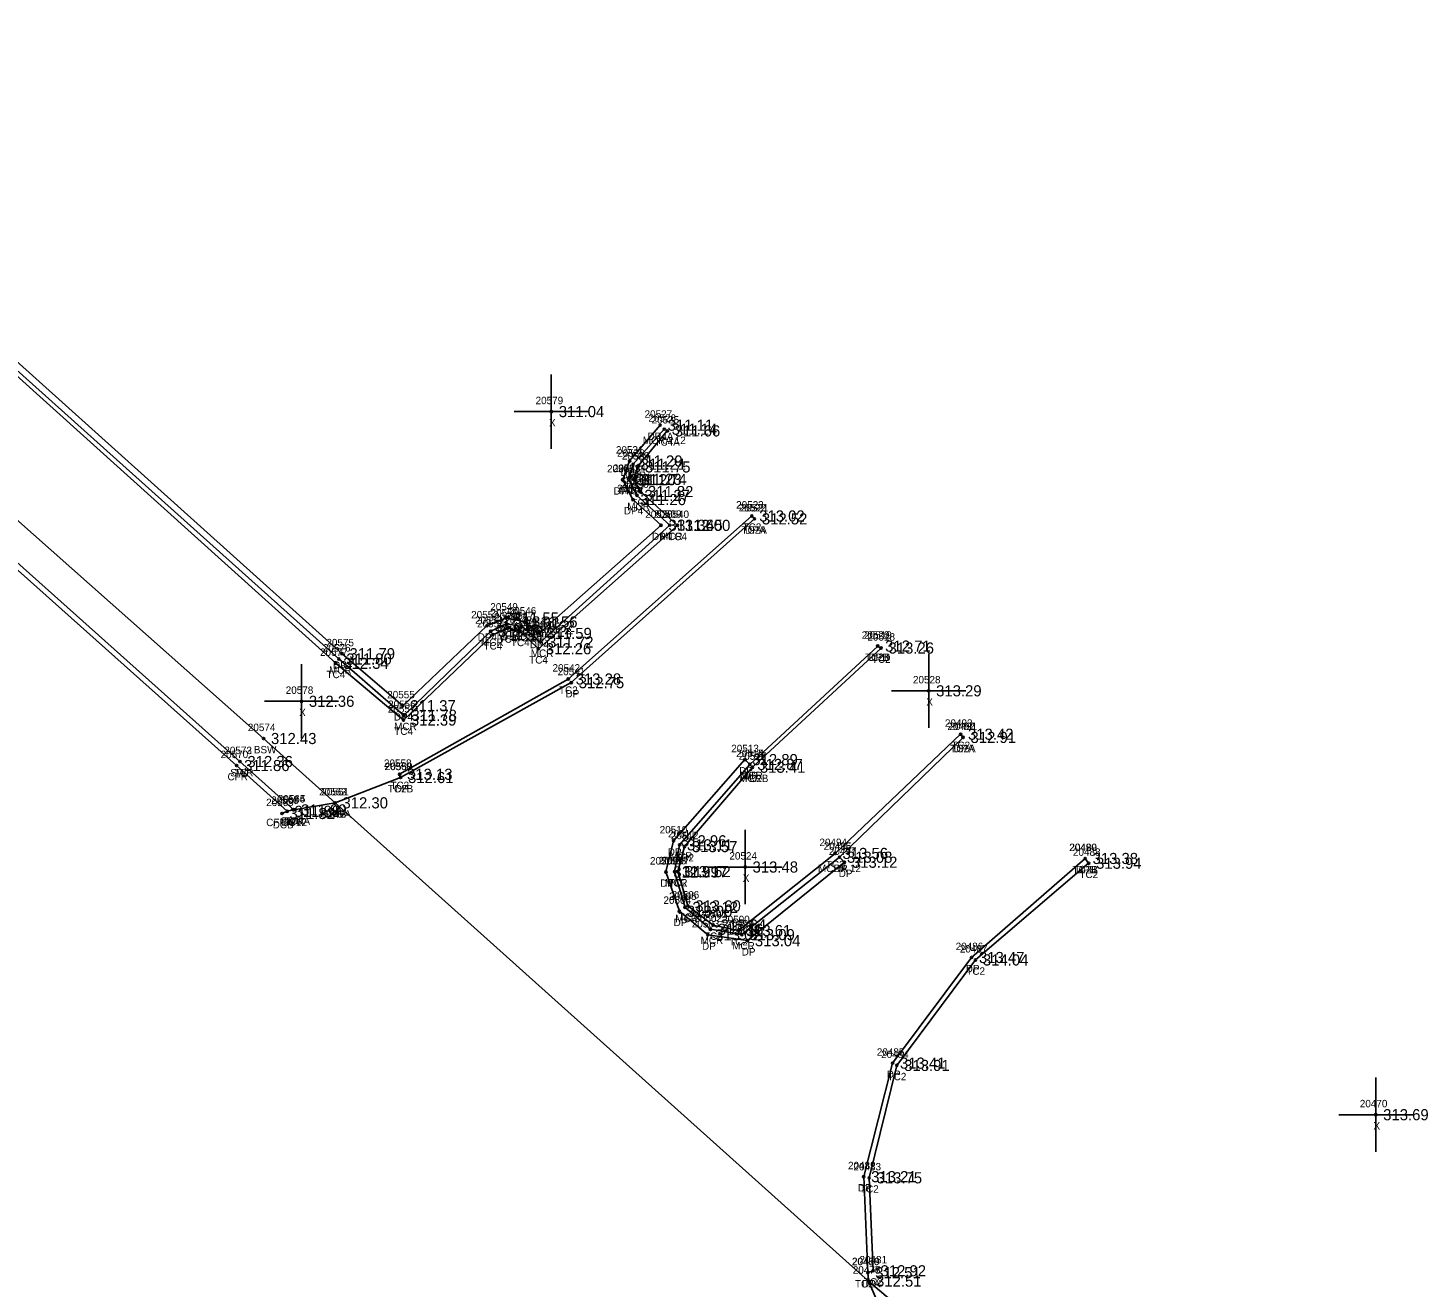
# Model space of a CAD drawing. Extents: x 1970242 to 1971082, y 803104 to 803947.
# Drawn here: x 1970893.2 to 1971082, y 803233.1 to 803402.9 of the extents above; entities that cross this region are included whole.
import ezdxf

# ---------------------------------------------------------------- set-up
doc = ezdxf.new("R2010")
doc.units = 0
for name, color, linetype in [('RD_DTM_BkLn2', 7, 'Continuous'), ('RD_EX_Conc', 7, 'Continuous'), ('RD_EX_Conc_txCode', 7, 'Continuous'), ('RD_EX_Driveway', 7, 'Continuous'), ('RD_EX_Driveway_txCode', 7, 'Continuous'), ('RD_EX_Misc', 7, 'Continuous'), ('RD_EX_Misc_txCode', 7, 'Continuous'), ('RD_EX_TX_Conc_ELEV', 7, 'Continuous'), ('RD_EX_TX_Driveway_ELEV', 7, 'Continuous'), ('RD_EX_TX_Misc_ELEV', 7, 'Continuous'), ('RD_SMD_Locator', 7, 'Continuous')]:
    doc.layers.add(name, color=color, linetype=linetype)

msp = doc.modelspace()

# ---------------------------------------------------------------- linework, layer by layer
at = {"layer": 'RD_DTM_BkLn2'}
for points in [[(1970979.45, 803348.6), (1970975.44, 803343.74), (1970974.92, 803342.04), (1970975.83, 803340.42), (1970980.81, 803335.86), (1970962.06, 803319.23), (1970959.6, 803321.58), (1970957.93, 803322.04), (1970955.92, 803321.12), (1970943.88, 803309.62), (1970934.75, 803317.27), (1970863.04, 803381.85), (1970875.59, 803396.45), (1970876.91, 803399.01), (1970875, 803401.36), (1970872.33, 803401.4), (1970870.6, 803400), (1970848.18, 803375.38), (1970847.84, 803375.76)], [(1970929.07, 803297.51), (1970921.83, 803304.03), (1970847.23, 803370.61)], [(1970991.2, 803336.74), (1970990.84, 803337.13), (1970966.09, 803315.15), (1970943.35, 803302.31), (1970943.49, 803301.87)], [(1971019.33, 803307.28), (1971018.99, 803307.71), (1971002.07, 803291.64), (1970989.03, 803281.24), (1970985.63, 803281.99), (1970982.22, 803284.57), (1970980.86, 803289.19), (1970981.77, 803292.56), (1970990.93, 803303.26), (1971008.27, 803319.33), (1971007.82, 803319.59)], [(1971006.48, 803235.13), (1971007.2, 803235.38), (1971006.67, 803247.91), (1971010.39, 803263.06), (1971021, 803277.28), (1971036.26, 803290.32), (1971035.79, 803290.96)]]:
    msp.add_lwpolyline(points, dxfattribs=at)
at = {"layer": 'RD_EX_Conc'}
for points in [[(1970979.04, 803348.83), (1970974.85, 803344.11), (1970974.24, 803342.07), (1970975.36, 803339.91), (1970979.77, 803335.89), (1970962.36, 803320.13), (1970959.86, 803322.22), (1970957.77, 803322.59), (1970955.64, 803321.59), (1970943.94, 803310.25), (1970935.16, 803317.85), (1970863.83, 803381.77), (1970876.22, 803396.22), (1970877.45, 803398.76), (1970875.12, 803402), (1970872.08, 803402.04), (1970870.03, 803400.53), (1970847.84, 803375.76)], [(1970934.65, 803298.46), (1970925.01, 803307.13), (1970847.03, 803376.25)], [(1970929.07, 803297.51), (1970921.83, 803304.03), (1970847.23, 803370.61)], [(1970928.19, 803297.32), (1970921.38, 803303.49), (1970847.31, 803369.61)], [(1971002.67, 803291.13), (1970989.5, 803280.69), (1970985.26, 803281.42), (1970981.84, 803284.37), (1970980.44, 803289.18), (1970981.1, 803292.8), (1970990.58, 803303.64), (1970990.93, 803303.26)], [(1971009.74, 803224.24), (1971010.01, 803224.85), (1971010.25, 803225.52), (1971006.59, 803233.99), (1970934.65, 803298.46), (1970929.07, 803297.51), (1970928.19, 803297.32), (1970927.5, 803297.02)], [(1971021.27, 803215.68), (1971024.17, 803219.06), (1971006.59, 803233.99)]]:
    msp.add_lwpolyline(points, dxfattribs=at)
at = {"layer": 'RD_EX_Driveway'}
for points in [[(1970978.49, 803349.37), (1970974.36, 803344.54), (1970973.43, 803342.01), (1970974.82, 803339.34), (1970978.6, 803335.88), (1970962.13, 803321.3), (1970960.21, 803322.85), (1970957.7, 803323.38), (1970955.12, 803322.32), (1970943.79, 803311.55), (1970935.6, 803318.56), (1970864.97, 803381.97), (1970876.89, 803395.59), (1970878.3, 803398.67), (1970875.35, 803402.77), (1970871.74, 803402.91), (1970869.45, 803401.14), (1970846.9, 803376.22)], [(1970991.2, 803336.74), (1970966.5, 803314.66), (1970943.49, 803301.87), (1970934.65, 803298.46)], [(1971019.33, 803307.28), (1971002.67, 803291.13), (1971003.34, 803290.45), (1970990.26, 803279.88), (1970984.91, 803280.66), (1970981.08, 803283.84), (1970979.26, 803289.14), (1970980.29, 803293.34), (1970989.91, 803304.29), (1970990.58, 803303.64), (1971007.82, 803319.59)], [(1971006.59, 803233.99), (1971006.48, 803235.13), (1971005.93, 803248.07), (1971009.82, 803263.37), (1971020.47, 803277.61), (1971035.79, 803290.96)]]:
    msp.add_lwpolyline(points, dxfattribs=at)
at = {"layer": 'RD_EX_Misc'}
for p, q in [((1970963.81, 803346.2), (1970963.81, 803356.2)), ((1970958.81, 803351.2), (1970968.81, 803351.2)), ((1971014.69, 803308.56), (1971014.69, 803318.56)), ((1970930.12, 803307.15), (1970930.12, 803317.15)), ((1970925.12, 803312.15), (1970935.12, 803312.15)), ((1971009.69, 803313.56), (1971019.69, 803313.56)), ((1970989.94, 803284.81), (1970989.94, 803294.81)), ((1970984.94, 803289.81), (1970994.94, 803289.81)), ((1971074.97, 803251.42), (1971074.97, 803261.42)), ((1971069.97, 803256.42), (1971079.97, 803256.42))]:
    msp.add_line(p, q, dxfattribs=at)
at = {"layer": 'RD_SMD_Locator'}
for centre in [(1970963.81, 803351.2), (1970978.49, 803349.37), (1970979.04, 803348.83), (1970979.45, 803348.6), (1970974.36, 803344.54), (1970974.85, 803344.11), (1970975.44, 803343.74), (1970973.43, 803342.01), (1970974.24, 803342.07), (1970974.92, 803342.04), (1970975.36, 803339.91), (1970975.83, 803340.42), (1970974.82, 803339.34), (1970990.84, 803337.13), (1970991.2, 803336.74), (1970991.2, 803336.74), (1970978.6, 803335.88), (1970979.77, 803335.89), (1970980.81, 803335.86), (1970957.7, 803323.38), (1970955.12, 803322.32), (1970955.64, 803321.59), (1970955.92, 803321.12), (1970957.77, 803322.59), (1970957.93, 803322.04), (1970959.6, 803321.58), (1970959.86, 803322.22), (1970960.21, 803322.85), (1970962.13, 803321.3), (1970962.06, 803319.23), (1970962.36, 803320.13), (1971007.82, 803319.59), (1971007.82, 803319.59), (1971008.27, 803319.33), (1970934.75, 803317.27), (1970935.16, 803317.85), (1970935.6, 803318.56), (1970966.09, 803315.15), (1970966.5, 803314.66), (1971014.69, 803313.56), (1970930.12, 803312.15), (1970943.79, 803311.55), (1970943.94, 803310.25), (1970943.88, 803309.62), (1970925.01, 803307.13), (1971018.99, 803307.71), (1971019.33, 803307.28), (1971019.33, 803307.28), (1970989.91, 803304.29), (1970921.38, 803303.49), (1970921.83, 803304.03), (1970921.83, 803304.03), (1970943.35, 803302.31), (1970990.58, 803303.64), (1970990.58, 803303.64), (1970990.93, 803303.26), (1970990.93, 803303.26), (1970943.49, 803301.87), (1970943.49, 803301.87), (1970934.65, 803298.46), (1970934.65, 803298.46), (1970934.65, 803298.46), (1970927.5, 803297.02), (1970928.19, 803297.32), (1970928.19, 803297.32), (1970929.07, 803297.51), (1970929.07, 803297.51), (1970929.07, 803297.51), (1970980.29, 803293.34), (1970981.1, 803292.8), (1970981.77, 803292.56), (1971002.07, 803291.64), (1971002.67, 803291.13), (1971002.67, 803291.13), (1971035.79, 803290.96), (1971035.79, 803290.96), (1970979.26, 803289.14), (1970980.44, 803289.18), (1970980.86, 803289.19), (1970989.94, 803289.81), (1971003.34, 803290.45), (1971036.26, 803290.32), (1970981.08, 803283.84), (1970981.84, 803284.37), (1970982.22, 803284.57), (1970985.26, 803281.42), (1970985.63, 803281.99), (1970984.91, 803280.66), (1970989.03, 803281.24), (1970989.5, 803280.69), (1970990.26, 803279.88), (1971020.47, 803277.61), (1971021, 803277.28), (1971009.82, 803263.37), (1971010.39, 803263.06), (1971074.97, 803256.42), (1971005.93, 803248.07), (1971006.67, 803247.91), (1971006.48, 803235.13), (1971006.48, 803235.13), (1971007.2, 803235.38), (1971006.59, 803233.99), (1971006.59, 803233.99), (1971006.59, 803233.99)]:
    msp.add_circle(centre, 0.15, dxfattribs=at)

# ---------------------------------------------------------------- texts
at = {"layer": 'RD_EX_Conc_txCode'}
for s, p in [('20526', (1970976.9, 803349.83)), ('20525', (1970977.33, 803349.6)), ('MCRA 12', (1970976.14, 803346.83)), ('TC4A', (1970977.72, 803346.6)), ('20530', (1970972.69, 803345.11)), ('20529', (1970973.32, 803344.74)), ('20533', (1970972.12, 803343.07)), ('20534', (1970972.8, 803343.04)), ('MCR', (1970973.53, 803342.11)), ('20535', (1970973.71, 803341.42)), ('TC4', (1970974.19, 803341.74)), ('MCR', (1970972.92, 803340.07)), ('20536', (1970973.22, 803340.91)), ('TC4', (1970973.67, 803340.04)), ('MCR', (1970974.05, 803337.91)), ('TC4', (1970974.59, 803338.42)), ('20523', (1970988.73, 803338.13)), ('20522', (1970989.08, 803337.74)), ('20539', (1970977.65, 803336.89)), ('20540', (1970978.66, 803336.86)), ('MCR', (1970978.46, 803333.89)), ('TC4', (1970979.57, 803333.86)), ('TC2A', (1970989.46, 803334.74)), ('TC2', (1970989.6, 803335.13)), ('20553', (1970953.53, 803322.59)), ('20554', (1970953.8, 803322.12)), ('20550', (1970955.62, 803323.59)), ('20551', (1970956.09, 803323.04)), ('20548', (1970957.48, 803322.58)), ('20547', (1970957.74, 803323.22)), ('MCR', (1970956.46, 803320.59)), ('MCR', (1970958.55, 803320.22)), ('20545', (1970959.94, 803320.23)), ('20544', (1970960.24, 803321.13)), ('20519', (1971005.99, 803320.59)), ('20518', (1971006.43, 803320.33)), ('20576', (1970933.01, 803318.85)), ('MCR', (1970954.33, 803319.59)), ('TC4', (1970954.67, 803319.12)), ('TC4', (1970956.69, 803320.04)), ('TC4', (1970958.36, 803319.58)), ('20577', (1970932.63, 803318.27)), ('TC4', (1970960.82, 803317.23)), ('MCR', (1970961.04, 803318.13)), ('TC2B', (1971006.11, 803317.59)), ('TC2', (1971007.03, 803317.33)), ('TC4', (1970933.5, 803315.27)), ('MCR', (1970933.84, 803315.85)), ('20542', (1970963.97, 803316.15)), ('TC2', (1970964.84, 803313.15)), ('20556', (1970941.8, 803311.25)), ('20557', (1970941.76, 803310.62)), ('20574', (1970922.89, 803308.13)), ('TC4', (1970942.63, 803307.62)), ('MCR', (1970942.62, 803308.25)), ('20493', (1971016.88, 803308.71)), ('20492', (1971017.21, 803308.28)), ('BSW', (1970923.7, 803305.13)), ('TC2A', (1971017.6, 803305.28)), ('TC2', (1971017.75, 803305.71)), ('20570', (1970919.22, 803304.49)), ('20572', (1970919.72, 803305.03)), ('20573', (1970919.72, 803305.03)), ('20558', (1970941.24, 803303.31)), ('20514', (1970988.74, 803304.64)), ('20516', (1970989.07, 803304.26)), ('20517', (1970989.09, 803304.26)), ('CFR', (1970920.15, 803301.49)), ('SWR', (1970920.52, 803302.03)), ('TC', (1970921.04, 803302.03)), ('20560', (1970941.31, 803302.87)), ('MCR', (1970989.26, 803301.64)), ('20562', (1970932.51, 803299.46)), ('20563', (1970932.51, 803299.46)), ('TC2B', (1970941.77, 803299.87)), ('TC2', (1970942.11, 803300.31)), ('MCRB', (1970989.14, 803301.26)), ('TC2', (1970989.69, 803301.26)), ('20569', (1970925.36, 803298.02)), ('20567', (1970926.05, 803298.32)), ('20568', (1970926.05, 803298.32)), ('20566', (1970926.91, 803298.51)), ('20564', (1970926.93, 803298.51)), ('20565', (1970926.93, 803298.51)), ('BSWA', (1970932.85, 803296.46)), ('DC', (1970933.87, 803296.46)), ('CFRA 12', (1970925.37, 803295.32)), ('DCB', (1970926.25, 803295.02)), ('SWRA', (1970927.27, 803295.51)), ('DC', (1970927.41, 803295.32)), ('TCA', (1970927.79, 803295.51)), ('DC', (1970928.29, 803295.51)), ('20511', (1970979.55, 803293.8)), ('20512', (1970979.93, 803293.56)), ('20494', (1970999.96, 803292.64)), ('20496', (1971000.53, 803292.13)), ('20489', (1971033.67, 803291.96)), ('20508', (1970978.28, 803290.18)), ('20507', (1970978.7, 803290.19)), ('MCR', (1970979.79, 803290.8)), ('TC2', (1970980.52, 803290.56)), ('20488', (1971034.14, 803291.32)), ('MCRA 12', (1970999.76, 803289.13)), ('TC2', (1971000.83, 803289.64)), ('TC2B', (1971034.08, 803288.96)), ('TC2', (1971035.01, 803288.32)), ('MCR', (1970979.13, 803287.18)), ('TC2', (1970979.61, 803287.19)), ('20505', (1970979.68, 803285.37)), ('20506', (1970980.03, 803285.57)), ('TC2', (1970980.97, 803282.57)), ('20502', (1970983.1, 803282.42)), ('20501', (1970983.76, 803282.99)), ('MCR', (1970980.53, 803282.37)), ('20500', (1970986.84, 803282.24)), ('20499', (1970987.39, 803281.69)), ('MCR', (1970983.94, 803279.42)), ('TC2', (1970984.39, 803279.99)), ('TC2', (1970987.79, 803279.24)), ('MCR', (1970988.19, 803278.69)), ('20487', (1971018.89, 803278.28)), ('TC2', (1971019.76, 803275.28)), ('20484', (1971008.28, 803264.06)), ('TC2', (1971009.15, 803261.06)), ('20483', (1971004.55, 803248.91)), ('TC2', (1971005.43, 803245.91)), ('20480', (1971004.33, 803236.13)), ('20481', (1971005.36, 803236.38)), ('20476', (1971004.45, 803234.99)), ('20477', (1971004.47, 803234.99)), ('TC2', (1971005.95, 803233.38)), ('TC2A', (1971004.75, 803233.13))]:
    msp.add_text(s, height=1, dxfattribs=at).set_placement(p)
at = {"layer": 'RD_EX_Driveway_txCode'}
for s, p in [('20527', (1970976.38, 803350.37)), ('DP4A', (1970976.78, 803347.37)), ('20531', (1970972.52, 803345.54)), ('20532', (1970971.32, 803343.01)), ('DP4', (1970973.13, 803342.54)), ('DP4', (1970972.21, 803340.01)), ('20537', (1970972.7, 803340.34)), ('DP4', (1970973.59, 803337.34)), ('20521', (1970989.36, 803337.74)), ('20538', (1970976.48, 803336.88)), ('DP4', (1970977.37, 803333.88)), ('DPA', (1970989.93, 803334.74)), ('20549', (1970955.58, 803324.38)), ('20552', (1970953, 803323.32)), ('20546', (1970958.06, 803323.85)), ('20543', (1970960.02, 803322.3)), ('DP4', (1970953.89, 803320.32)), ('DP4', (1970956.47, 803321.38)), ('DP4', (1970958.98, 803320.85)), ('20520', (1971005.67, 803320.59)), ('20575', (1970933.48, 803319.56)), ('DP4', (1970960.91, 803319.3)), ('DP4', (1970934.37, 803316.56)), ('DPB', (1971006.57, 803317.59)), ('20541', (1970964.66, 803315.66)), ('DP', (1970965.72, 803312.66)), ('20555', (1970941.68, 803312.55)), ('DP4', (1970942.57, 803309.55)), ('20491', (1971017.49, 803308.28)), ('20513', (1970988.07, 803305.29)), ('DPA', (1971018.06, 803305.28)), ('20515', (1970988.74, 803304.64)), ('20559', (1970941.37, 803302.87)), ('DP', (1970989.13, 803302.29)), ('DP', (1970989.8, 803301.64)), ('20561', (1970932.8, 803299.46)), ('DP', (1970942.71, 803299.87)), ('DPB', (1970933.4, 803296.46)), ('20510', (1970978.42, 803294.34)), ('20495', (1971000.55, 803292.13)), ('20490', (1971033.63, 803291.96)), ('20509', (1970977.11, 803290.14)), ('DP', (1970979.51, 803291.34)), ('20497', (1971001.23, 803291.45)), ('DP', (1971001.89, 803289.13)), ('DP', (1971002.56, 803288.45)), ('DPB', (1971034.54, 803288.96)), ('DP', (1970978.48, 803287.14)), ('20504', (1970978.93, 803284.84)), ('DP', (1970980.3, 803281.84)), ('20503', (1970982.75, 803281.66)), ('20498', (1970988.14, 803280.88)), ('DP', (1970984.13, 803278.66)), ('DP', (1970989.48, 803277.88)), ('20486', (1971018.33, 803278.61)), ('DP', (1971019.69, 803275.61)), ('20485', (1971007.7, 803264.37)), ('DP', (1971009.04, 803261.37)), ('20482', (1971003.81, 803249.07)), ('DP', (1971005.15, 803246.07)), ('20479', (1971004.37, 803236.13)), ('20478', (1971004.47, 803234.99)), ('DP', (1971005.7, 803233.13))]:
    msp.add_text(s, height=1, dxfattribs=at).set_placement(p)
at = {"layer": 'RD_EX_Misc_txCode'}
for s, p in [('20579', (1970961.69, 803352.2)), ('X', (1970963.5, 803349.2)), ('20528', (1971012.57, 803314.56)), ('20578', (1970928, 803313.15)), ('X', (1971014.37, 803311.56)), ('X', (1970929.81, 803310.15)), ('20524', (1970987.82, 803290.81)), ('X', (1970989.62, 803287.81)), ('20470', (1971072.82, 803257.42)), ('X', (1971074.66, 803254.42))]:
    msp.add_text(s, height=1, dxfattribs=at).set_placement(p)
at = {"layer": 'RD_EX_TX_Conc_ELEV'}
for s, p in [('311.14', (1970980.04, 803348.08)), ('311.66', (1970980.45, 803347.85)), ('311.21', (1970975.85, 803343.36)), ('311.75', (1970976.44, 803342.99)), ('311.23', (1970975.24, 803341.32)), ('311.74', (1970975.92, 803341.29)), ('311.27', (1970976.36, 803339.16)), ('311.82', (1970976.83, 803339.67)), ('311.45', (1970980.77, 803335.14)), ('312.00', (1970981.81, 803335.11)), ('313.02', (1970991.84, 803336.38)), ('312.52', (1970992.2, 803335.99)), ('311.61', (1970958.77, 803321.84)), ('311.58', (1970956.64, 803320.84)), ('312.17', (1970956.92, 803320.37)), ('312.15', (1970958.93, 803321.29)), ('312.14', (1970960.6, 803320.83)), ('311.62', (1970960.86, 803321.47)), ('312.26', (1970963.06, 803318.48)), ('311.72', (1970963.36, 803319.38)), ('312.71', (1971008.82, 803318.84)), ('313.26', (1971009.27, 803318.58)), ('312.34', (1970935.75, 803316.52)), ('311.80', (1970936.16, 803317.1)), ('313.28', (1970967.09, 803314.4)), ('312.39', (1970944.88, 803308.87)), ('311.78', (1970944.94, 803309.5)), ('313.42', (1971019.99, 803306.96)), ('312.91', (1971020.33, 803306.53)), ('312.43', (1970926.01, 803306.38)), ('311.86', (1970922.38, 803302.74)), ('312.36', (1970922.83, 803303.28)), ('312.36', (1970922.83, 803303.28)), ('312.87', (1970991.58, 803302.89)), ('313.13', (1970944.35, 803301.56)), ('312.61', (1970944.49, 803301.12)), ('313.41', (1970991.93, 803302.51)), ('313.41', (1970991.93, 803302.51)), ('312.30', (1970935.65, 803297.71)), ('312.30', (1970935.65, 803297.71)), ('311.82', (1970928.5, 803296.27)), ('311.88', (1970929.19, 803296.57)), ('311.88', (1970929.19, 803296.57)), ('311.99', (1970930.07, 803296.76)), ('311.99', (1970930.07, 803296.76)), ('311.99', (1970930.07, 803296.76)), ('313.11', (1970982.1, 803292.05)), ('313.57', (1970982.77, 803291.81)), ('313.56', (1971003.07, 803290.89)), ('313.08', (1971003.67, 803290.38)), ('313.38', (1971036.79, 803290.21)), ('313.94', (1971037.26, 803289.57)), ('313.17', (1970981.44, 803288.43)), ('313.62', (1970981.86, 803288.44)), ('313.60', (1970983.22, 803283.82)), ('313.12', (1970982.84, 803283.62)), ('313.16', (1970986.26, 803280.67)), ('313.64', (1970986.63, 803281.24)), ('313.61', (1970990.03, 803280.49)), ('313.09', (1970990.5, 803279.94)), ('314.04', (1971022, 803276.53)), ('313.91', (1971011.39, 803262.31)), ('313.75', (1971007.67, 803247.16)), ('312.51', (1971007.48, 803234.38)), ('312.51', (1971007.59, 803233.24)), ('312.51', (1971007.59, 803233.24)), ('312.92', (1971008.2, 803234.63))]:
    msp.add_text(s, height=1.5, dxfattribs=at).set_placement(p)
at = {"layer": 'RD_EX_TX_Driveway_ELEV'}
for s, p in [('311.11', (1970979.49, 803348.62)), ('311.20', (1970975.36, 803343.79)), ('311.20', (1970974.43, 803341.26)), ('311.26', (1970975.82, 803338.59)), ('311.36', (1970979.6, 803335.13)), ('312.52', (1970992.2, 803335.99)), ('311.58', (1970956.12, 803321.57)), ('311.55', (1970958.7, 803322.63)), ('311.56', (1970961.21, 803322.1)), ('311.59', (1970963.13, 803320.55)), ('311.79', (1970936.6, 803317.81)), ('312.71', (1971008.82, 803318.84)), ('312.75', (1970967.5, 803313.91)), ('311.37', (1970944.79, 803310.8)), ('312.91', (1971020.33, 803306.53)), ('312.89', (1970990.91, 803303.54)), ('312.87', (1970991.58, 803302.89)), ('312.61', (1970944.49, 803301.12)), ('312.30', (1970935.65, 803297.71)), ('312.96', (1970981.29, 803292.59)), ('313.08', (1971003.67, 803290.38)), ('313.12', (1971004.34, 803289.7)), ('313.38', (1971036.79, 803290.21)), ('312.99', (1970980.26, 803288.39)), ('313.00', (1970982.08, 803283.09)), ('313.02', (1970985.91, 803279.91)), ('313.04', (1970991.26, 803279.13)), ('313.47', (1971021.47, 803276.86)), ('313.41', (1971010.82, 803262.62)), ('313.21', (1971006.93, 803247.32)), ('312.51', (1971007.48, 803234.38)), ('312.51', (1971007.59, 803233.24))]:
    msp.add_text(s, height=1.5, dxfattribs=at).set_placement(p)
at = {"layer": 'RD_EX_TX_Misc_ELEV'}
for s, p in [('311.04', (1970964.81, 803350.45)), ('313.29', (1971015.69, 803312.81)), ('312.36', (1970931.12, 803311.4)), ('313.48', (1970990.94, 803289.06)), ('313.69', (1971075.97, 803255.67))]:
    msp.add_text(s, height=1.5, dxfattribs=at).set_placement(p)

doc.saveas('drawing.dxf')
